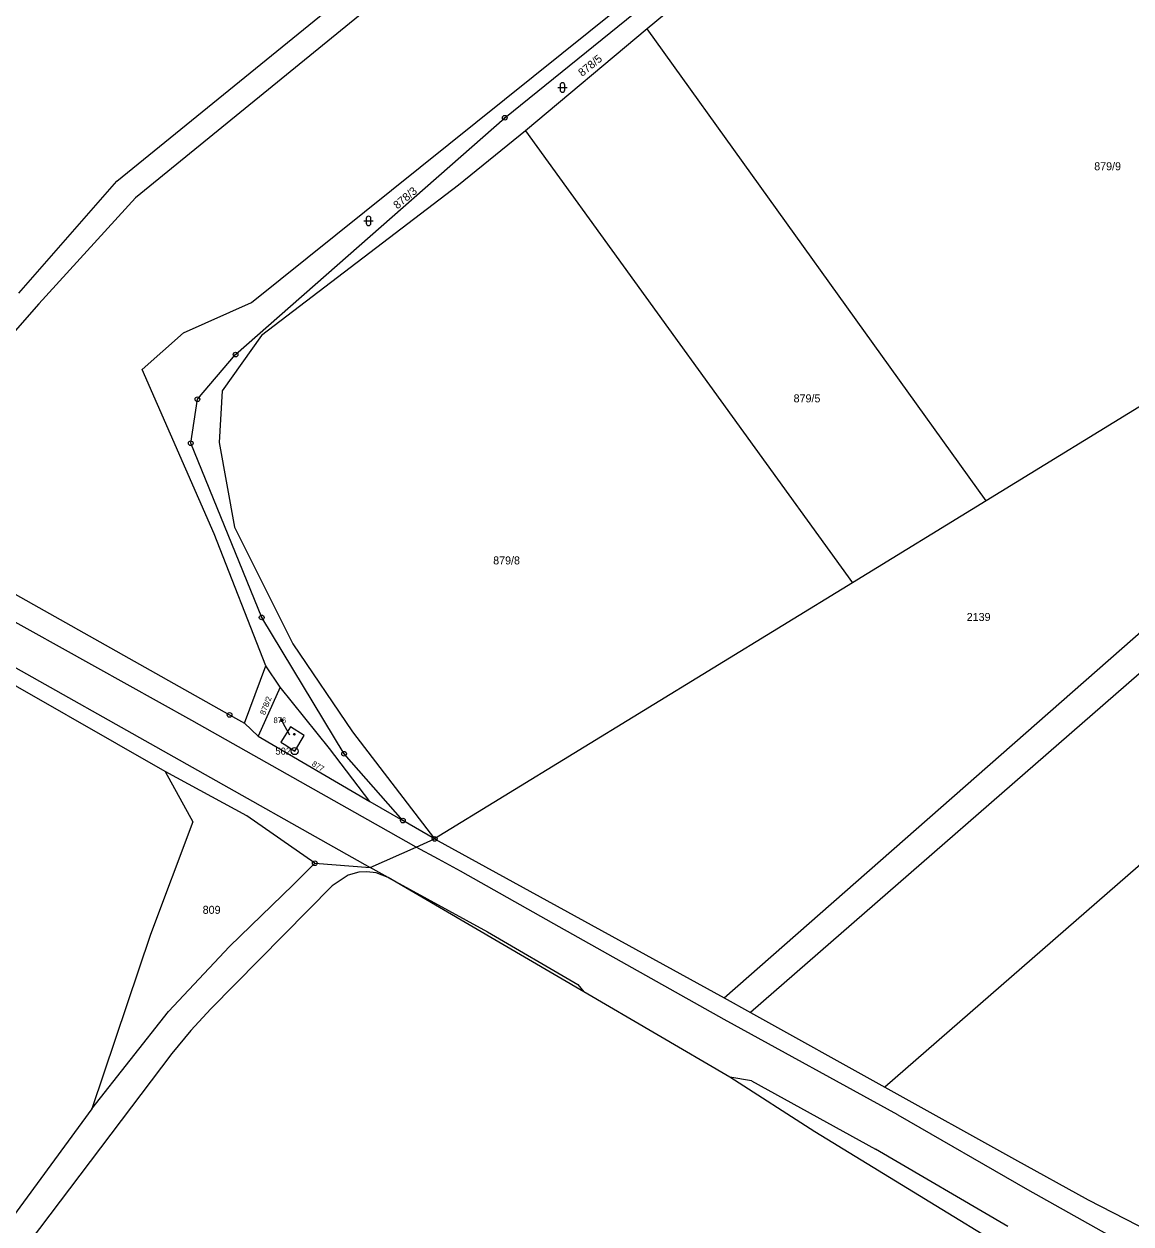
# Model space of a CAD drawing. Extents: x -504988 to -494607, y -1123820 to -1114018.
# Drawn here: x -502590.5 to -502355.4, y -1120247.9 to -1119993 of the extents above; entities that cross this region are included whole.
import ezdxf

# ---------------------------------------------------------------- set-up
doc = ezdxf.new("R2010")
doc.units = 0
for name, color, linetype in [('Hranice parcel', 7, 'Continuous'), ('Parcelní čísla', 7, 'Continuous'), ('Pop  PČ popisy', 7, 'Continuous'), ('Vnitřní kresba', 7, 'Continuous'), ('Značky bodu BP', 7, 'Continuous'), ('Značky budov', 7, 'Continuous'), ('Značky kultur', 7, 'Continuous')]:
    doc.layers.add(name, color=color, linetype=linetype)

msp = doc.modelspace()

# ---------------------------------------------------------------- linework, layer by layer
at = {"layer": 'Hranice parcel'}
for p, q in [((-502458.12, -1119994.04), (-502484.02, -1120015.68)), ((-502386.15, -1120094.27), (-502458.12, -1119994.04)), ((-502484.02, -1120015.68), (-502414.55, -1120111.69)), ((-502271.25, -1120023.8), (-502386.15, -1120094.27)), ((-502386.15, -1120094.27), (-502414.55, -1120111.69)), ((-502414.55, -1120111.69), (-502503.28, -1120166.11)), ((-502543.64, -1120141.5), (-502539.17, -1120129.38)), ((-502536.09, -1120133.88), (-502539.17, -1120129.38)), ((-502536.09, -1120133.88), (-502540.77, -1120144.32)), ((-502543.64, -1120141.5), (-502540.77, -1120144.32)), ((-502540.77, -1120144.32), (-502517.02, -1120158.2)), ((-502517.02, -1120158.2), (-502510.03, -1120162.22)), ((-502503.28, -1120166.11), (-502510.03, -1120162.22)), ((-502503.28, -1120166.11), (-502441.81, -1120199.89)), ((-502528.74, -1120171.28), (-502516.98, -1120172.21)), ((-502513.12, -1120174.32), (-502516.98, -1120172.21)), ((-502441.81, -1120199.89), (-502436.23, -1120202.99)), ((-502436.23, -1120202.99), (-502407.66, -1120218.87))]:
    msp.add_line(p, q, dxfattribs=at)
for points in [[(-502396.12, -1119890.8), (-502566.84, -1120029.94), (-502587.36, -1120052.45), (-502608.42, -1120076.47), (-502633.38, -1120096.81)], [(-502334.35, -1119889.76), (-502274.39, -1119970.13), (-502214.42, -1120050.5), (-502311.04, -1120134.69), (-502407.66, -1120218.87)], [(-502539.17, -1120129.38), (-502550.09, -1120101.33), (-502565.41, -1120066.4), (-502556.62, -1120058.59), (-502542.2, -1120052.17), (-502428.59, -1119960.97), (-502372.84, -1119914.3)], [(-502510.03, -1120162.22), (-502522.53, -1120148.04), (-502540.02, -1120119.07), (-502555.09, -1120082.05), (-502553.66, -1120072.7), (-502545.55, -1120063.24), (-502488.39, -1120012.91), (-502378.38, -1119923.93), (-502371.14, -1119917.24)], [(-502363.93, -1119915.42), (-502360.92, -1119919.32), (-502356.11, -1119924.82), (-502271.75, -1120010.63), (-502258.23, -1120024.92), (-502255.98, -1120027.81), (-502253.76, -1120034.16), (-502254.99, -1120043.43), (-502256.73, -1120046.58), (-502346.48, -1120124.79), (-502436.23, -1120202.99)], [(-502369.46, -1119920.13), (-502423.33, -1119965.12), (-502458.12, -1119994.04)], [(-502591.59, -1120050.18), (-502570.78, -1120026.41), (-502516.42, -1119982.14)], [(-502484.02, -1120015.68), (-502498.19, -1120027.24), (-502540.07, -1120059.19), (-502548.41, -1120070.95), (-502549.08, -1120081.9), (-502545.81, -1120099.86), (-502533.42, -1120124.68), (-502520.7, -1120143.37), (-502503.28, -1120166.11)], [(-502441.81, -1120199.89), (-502349.77, -1120118.99), (-502257.72, -1120038.08), (-502271.25, -1120023.8)], [(-502633.38, -1120096.81), (-502593.53, -1120113.47), (-502546.85, -1120139.78), (-502543.64, -1120141.5)], [(-502560.51, -1120151.82), (-502602.16, -1120127.99), (-502615.82, -1120121.36), (-502619, -1120119.82)], [(-502517.02, -1120158.2), (-502525.61, -1120146.91), (-502536.09, -1120133.88)], [(-502533.93, -1120142.32), (-502535.97, -1120145.57), (-502535.24, -1120146.02), (-502533.01, -1120147.47), (-502531, -1120144.15), (-502533.93, -1120142.32)], [(-502560.51, -1120151.82), (-502554.64, -1120162.49), (-502563.6, -1120186.41), (-502576.12, -1120223.5)], [(-502528.74, -1120171.28), (-502543.18, -1120161.25), (-502560.51, -1120151.82)], [(-502516.98, -1120172.21), (-502507.22, -1120167.87), (-502503.28, -1120166.11)], [(-502576.12, -1120223.5), (-502559.8, -1120202.77), (-502546.82, -1120188.98), (-502533.31, -1120175.91), (-502528.74, -1120171.28)], [(-502513.12, -1120174.32), (-502515.72, -1120173.34), (-502517.69, -1120173.1), (-502519.37, -1120173.2), (-502521.68, -1120173.83), (-502525.04, -1120176.07), (-502550.82, -1120202.21), (-502555.1, -1120206.84), (-502559.07, -1120211.74), (-502589.41, -1120251.77)], [(-502357.5, -1120268.13), (-502422.55, -1120228.33), (-502440.57, -1120216.74), (-502471.56, -1120198.62), (-502513.12, -1120174.32)], [(-502407.66, -1120218.87), (-502380.12, -1120234.18), (-502364.46, -1120242.81), (-502348.79, -1120250.85)], [(-502576.12, -1120223.5), (-502595.72, -1120250.16), (-502618.64, -1120277.36), (-502640.17, -1120296.95), (-502650.33, -1120307.7), (-502666.23, -1120326.22), (-502689.78, -1120350.38), (-502701.93, -1120358.98)]]:
    msp.add_lwpolyline(points, dxfattribs=at)
at = {"layer": 'Pop  PČ popisy'}
for p, q in [((-502535.02, -1120142.29), (-502535.96, -1120140.52)), ((-502535.96, -1120140.52), (-502535.35, -1120140.95)), ((-502535.96, -1120140.52), (-502535.95, -1120141.27)), ((-502534.07, -1120144.06), (-502535.02, -1120142.29))]:
    msp.add_line(p, q, dxfattribs=at)
at = {"layer": 'Vnitřní kresba'}
for p, q in [((-502554.82, -1120140.94), (-502596.11, -1120118)), ((-502600.8, -1120124.95), (-502558.71, -1120148.66)), ((-502513.08, -1120164.55), (-502554.82, -1120140.94)), ((-502558.71, -1120148.66), (-502516.98, -1120172.21)), ((-502507.22, -1120167.87), (-502513.08, -1120164.55)), ((-502502.45, -1120170.46), (-502507.22, -1120167.87)), ((-502497.78, -1120172.96), (-502502.45, -1120170.46)), ((-502513.12, -1120174.32), (-502492.05, -1120185.86)), ((-502477.98, -1120184.18), (-502497.78, -1120172.96)), ((-502441.82, -1120204.5), (-502477.98, -1120184.18)), ((-502492.05, -1120185.86), (-502472.88, -1120197.03)), ((-502472.88, -1120197.03), (-502471.56, -1120198.62)), ((-502404.92, -1120224.71), (-502441.82, -1120204.5)), ((-502436, -1120217.52), (-502440.57, -1120216.74)), ((-502436, -1120217.52), (-502409.63, -1120232.05)), ((-502404.92, -1120224.71), (-502377.34, -1120240.64)), ((-502381.52, -1120248.47), (-502409.63, -1120232.05)), ((-502377.34, -1120240.64), (-502341.34, -1120260.78))]:
    msp.add_line(p, q, dxfattribs=at)
at = {"layer": 'Značky bodu BP'}
for centre, radius in [((-502488.39, -1120012.91), 0.5), ((-502488.39, -1120012.91), 0.0303), ((-502545.55, -1120063.24), 0.5), ((-502545.55, -1120063.24), 0.0303), ((-502553.66, -1120072.7), 0.5), ((-502553.66, -1120072.7), 0.0303), ((-502555.09, -1120082.05), 0.5), ((-502555.09, -1120082.05), 0.0303), ((-502540.02, -1120119.07), 0.5), ((-502540.02, -1120119.07), 0.0303), ((-502546.85, -1120139.78), 0.5), ((-502546.85, -1120139.78), 0.0303), ((-502533.01, -1120147.47), 0.75), ((-502533.01, -1120147.47), 0.03), ((-502522.53, -1120148.04), 0.5), ((-502522.53, -1120148.04), 0.0303), ((-502510.03, -1120162.22), 0.5), ((-502510.03, -1120162.22), 0.0303), ((-502503.28, -1120166.11), 0.5), ((-502503.28, -1120166.11), 0.0303), ((-502528.74, -1120171.28), 0.5), ((-502528.74, -1120171.28), 0.0303)]:
    msp.add_circle(centre, radius, dxfattribs=at)
at = {"layer": 'Značky budov'}
msp.add_circle((-502533.08, -1120143.88), 0.175, dxfattribs=at)
at = {"layer": 'Značky kultur'}
for p, q in [((-502477.15, -1120006.49), (-502475.15, -1120006.49)), ((-502476.65, -1120005.99), (-502476.65, -1120006.99)), ((-502475.65, -1120006.99), (-502475.65, -1120005.99)), ((-502518.32, -1120034.83), (-502516.32, -1120034.83)), ((-502517.82, -1120034.33), (-502517.82, -1120035.33)), ((-502516.82, -1120035.33), (-502516.82, -1120034.33))]:
    msp.add_line(p, q, dxfattribs=at)
for centre, start, end in [((-502476.15, -1120005.99), 0, 180), ((-502476.15, -1120006.99), 180, 359.9879), ((-502517.32, -1120034.33), 0, 180), ((-502517.32, -1120035.33), 180, 359.9879)]:
    msp.add_arc(centre, 0.5, start, end, dxfattribs=at)

# ---------------------------------------------------------------- texts
at = {"layer": 'Parcelní čísla'}
for s, height, rotation, p in [('878/5', 1.7, 39, (-502471.94, -1120004.25)), ('878/3', 1.7, 40, (-502511.19, -1120032.41)), ('878/2', 1.2, 69, (-502539.31, -1120139.88)), ('877', 1.2, 329, (-502529.49, -1120150.51))]:
    msp.add_text(s, height=height, rotation=rotation, dxfattribs=at).set_placement(p)
for s, height, p in [('879/9', 1.7, (-502363.19, -1120024.07)), ('879/5', 1.7, (-502427.04, -1120073.38)), ('879/8', 1.7, (-502490.85, -1120107.81)), ('2139', 1.7, (-502390.27, -1120119.82)), ('876', 1.2, (-502537.51, -1120141.52)), ('809', 1.7, (-502552.55, -1120182.04))]:
    msp.add_text(s, height=height, dxfattribs=at).set_placement(p)
at = {"layer": 'Značky bodu BP'}
msp.add_text('502', height=1.5, dxfattribs=at).set_placement((-502537.11, -1120148.22))

doc.saveas('drawing.dxf')
